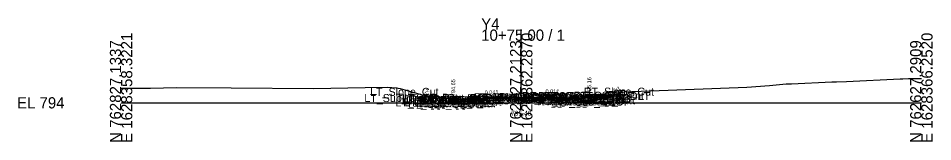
# Model space of a CAD drawing. Extents: x -26 to 203, y -10 to 3017.
# Drawn here: x -25.7 to 202.8, y 1490.3 to 1521.1 of the extents above; entities that cross this region are included whole.
import ezdxf

# ---------------------------------------------------------------- set-up
doc = ezdxf.new("R2010")
doc.units = 0
for name, color, linetype in [('Default', 7, 'Continuous'), ('Exist CMT Pavement', 7, 'Continuous'), ('Exist Cross Section Cell', 7, 'Continuous'), ('Exist XS Center Line Elevation Label', 7, 'Continuous'), ('Exist XS Ground Line', 7, 'Continuous'), ('Prop CMT Conc Surface', 7, 'Continuous'), ('Prop CMT Concrete Structures', 7, 'Continuous'), ('Prop CMT Pvmt Course 1', 7, 'Continuous'), ('Prop CMT Pvmt Course 1 CG', 7, 'Continuous'), ('Prop CMT Pvmt Course 1 Wedge', 7, 'Continuous'), ('Prop CMT Pvmt Course 2', 7, 'Continuous'), ('Prop CMT Pvmt Course 3', 7, 'Continuous'), ('Prop CMT Pvmt Surface', 7, 'Continuous'), ('Prop CMT Pvmt Wedge Surface 1', 7, 'Continuous'), ('Prop CMT Pvmt Wedge Surface 2', 7, 'Continuous'), ('Prop CMT Pvmt Wedge Surface 3', 7, 'Continuous'), ('Prop CMT Slope Grass', 7, 'Continuous'), ('Prop CMT Subgrade Earthwork', 7, 'Continuous'), ('Prop XS Hydro Elevations', 7, 'Continuous'), ('Prop XS SE Text', 7, 'Continuous'), ('Prop XS Side Slope Text', 7, 'Continuous'), ('Scratch_Level_0', 7, 'Continuous')]:
    doc.layers.add(name, color=color, linetype=linetype)

msp = doc.modelspace()

# ---------------------------------------------------------------- linework, layer by layer
at = {"layer": 'Exist CMT Pavement'}
for points in [[(100, 1501.4), (99.81, 1501.41), (95.3, 1501.2), (88.98, 1500.91), (88.16, 1500.85), (85.17, 1500.61)], [(100, 1501.4), (104.1, 1501.33), (110.97, 1501.22), (114.02, 1501.06), (114.86, 1501.03)], [(114.86, 1501.03), (114.86, 1501.03)]]:
    msp.add_lwpolyline(points, dxfattribs=at)
at = {"layer": 'Exist Cross Section Cell'}
for p, q in [((100, 1500), (100, 1518.27)), ((0, 1500), (100, 1500)), ((100, 1500), (200, 1500))]:
    msp.add_line(p, q, dxfattribs=at)
at = {"layer": 'Exist XS Ground Line'}
msp.add_lwpolyline([(0, 1503.66), (7.35, 1503.64), (13.85, 1503.81), (27.47, 1503.77), (48.05, 1503.6), (61.03, 1503.8), (66.57, 1503.94), (68.77, 1503.75), (69.78, 1503.53), (75.58, 1501.87), (77.91, 1501.34), (80.15, 1501.12), (82.88, 1501.17), (84.63, 1500.87), (85.17, 1500.61), (88.16, 1500.85), (88.98, 1500.91), (95.3, 1501.2), (99.81, 1501.41), (104.1, 1501.33), (110.97, 1501.22), (114.02, 1501.06), (114.86, 1501.03), (115.37, 1501.41), (116.27, 1501.41), (118.87, 1501.42), (121.21, 1502.41), (122.08, 1502.79), (124.74, 1503.09), (125.62, 1503.2), (126.12, 1502.7), (127.62, 1502.78), (132.29, 1502.97), (156.36, 1503.86), (162.04, 1504.34), (166.18, 1504.7), (166.49, 1504.72), (167.55, 1504.77), (177.63, 1505.2), (178.77, 1505.2), (181.32, 1505.28), (194.67, 1505.97), (195.39, 1505.97), (196.8, 1506.05), (200, 1506.09)], dxfattribs=at)
at = {"layer": 'Prop CMT Conc Surface'}
for points in [[(117, 1501.16), (117, 1501.66), (117.5, 1501.66)], [(83, 1500.65), (83, 1501.15), (82.5, 1501.15)], [(85, 1500.81), (83, 1500.65)], [(115, 1501.26), (117, 1501.16)]]:
    msp.add_lwpolyline(points, dxfattribs=at)
at = {"layer": 'Prop CMT Concrete Structures'}
for points in [[(115, 1501.26), (117, 1501.16), (117, 1501.66), (117.5, 1501.66)], [(117.5, 1501.66), (117.5, 1500.65), (115, 1500.68)], [(117.5, 1501.66), (117.5, 1501.32)], [(122.5, 1501.42), (122.5, 1501.76)], [(85, 1500.81), (83, 1500.65), (83, 1501.15), (82.5, 1501.15)], [(82.5, 1501.15), (82.5, 1500.12), (85, 1500.23)], [(85, 1500.23), (85, 1500.81)], [(115, 1500.68), (115, 1501.26)], [(117.5, 1501.32), (122.5, 1501.42)]]:
    msp.add_lwpolyline(points, dxfattribs=at)
at = {"layer": 'Prop CMT Pvmt Course 1'}
for points in [[(100, 1501.43), (85, 1500.81)], [(85, 1500.81), (85, 1500.56)], [(85, 1500.56), (85.17, 1500.57)], [(85.17, 1500.69), (100, 1501.31)], [(85.17, 1500.57), (85.17, 1500.69)], [(100, 1501.18), (100, 1501.43)], [(100, 1501.43), (115, 1501.26)], [(100, 1501.18), (100, 1501.43)], [(100, 1501.31), (100, 1501.18), (100, 1501.18)], [(114.86, 1501.14), (100, 1501.31)], [(100, 1501.31), (100, 1501.18), (100, 1501.18)], [(114.86, 1501.01), (114.86, 1501.14)], [(115, 1501.01), (114.86, 1501.01)], [(115, 1501.26), (115, 1501.01)]]:
    msp.add_lwpolyline(points, dxfattribs=at)
at = {"layer": 'Prop CMT Pvmt Course 1 CG'}
for points in [[(85, 1500.23), (82, 1500.1), (81.65, 1499.75)], [(81.65, 1499.75), (85, 1499.89)], [(85, 1499.89), (85, 1500.23)], [(115, 1500.68), (118, 1500.64), (118.34, 1500.31)], [(115, 1500.34), (115, 1500.68)], [(118.34, 1500.31), (115, 1500.34)]]:
    msp.add_lwpolyline(points, dxfattribs=at)
at = {"layer": 'Prop CMT Pvmt Course 1 Wedge'}
for points in [[(85.17, 1500.69), (87.3, 1500.78)], [(87.3, 1500.78), (85.17, 1500.61)], [(85.17, 1500.61), (85.17, 1500.69)], [(114.86, 1501.03), (114.02, 1501.06), (112.01, 1501.17)], [(112.01, 1501.17), (114.02, 1501.15)], [(114.02, 1501.15), (114.86, 1501.14)], [(114.86, 1501.14), (114.86, 1501.03), (114.86, 1501.03)]]:
    msp.add_lwpolyline(points, dxfattribs=at)
at = {"layer": 'Prop CMT Pvmt Course 2'}
for points in [[(85.17, 1500.57), (85, 1500.56)], [(85, 1500.56), (85, 1500.23)], [(85, 1500.23), (85.17, 1500.23)], [(85.17, 1500.23), (85.17, 1500.57)], [(114.86, 1500.68), (114.86, 1501.01)], [(114.86, 1501.01), (115, 1501.01)], [(115, 1500.68), (114.86, 1500.68)], [(115, 1501.01), (115, 1500.68)]]:
    msp.add_lwpolyline(points, dxfattribs=at)
at = {"layer": 'Prop CMT Pvmt Course 3'}
for points in [[(85.17, 1500.23), (85, 1500.23)], [(85, 1500.23), (85, 1499.89)], [(85, 1499.89), (85.17, 1499.9)], [(85.17, 1499.9), (85.17, 1500.23)], [(114.86, 1500.68), (115, 1500.68)], [(114.86, 1500.34), (114.86, 1500.68)], [(115, 1500.34), (114.86, 1500.34)], [(115, 1500.68), (115, 1500.34)]]:
    msp.add_lwpolyline(points, dxfattribs=at)
at = {"layer": 'Prop CMT Pvmt Surface'}
for points in [[(100, 1501.43), (85, 1500.81)], [(100, 1501.43), (115, 1501.26)]]:
    msp.add_lwpolyline(points, dxfattribs=at)
at = {"layer": 'Prop CMT Pvmt Wedge Surface 1'}
for points in [[(85, 1500.56), (85, 1500.81)], [(85.17, 1500.57), (85, 1500.56)], [(100, 1501.31), (85.17, 1500.69)], [(85.17, 1500.69), (85.17, 1500.57)], [(100, 1501.31), (114.86, 1501.14)], [(114.86, 1501.14), (114.86, 1501.01)], [(114.86, 1501.01), (115, 1501.01)], [(115, 1501.01), (115, 1501.26)]]:
    msp.add_lwpolyline(points, dxfattribs=at)
at = {"layer": 'Prop CMT Pvmt Wedge Surface 2'}
for points in [[(100, 1501.18), (85, 1500.56)], [(85, 1500.56), (85, 1500.81)], [(100, 1501.18), (115, 1501.01)], [(115, 1501.01), (115, 1501.26)]]:
    msp.add_lwpolyline(points, dxfattribs=at)
at = {"layer": 'Prop CMT Pvmt Wedge Surface 3'}
for points in [[(100, 1500.85), (85, 1500.23)], [(85, 1500.23), (85, 1500.81)], [(100, 1500.85), (115, 1500.68)], [(115, 1500.68), (115, 1501.26)]]:
    msp.add_lwpolyline(points, dxfattribs=at)
at = {"layer": 'Prop CMT Slope Grass'}
for p, q in [((75.93, 1501.79), (77, 1501.26)), ((123, 1501.77), (125.7, 1503.12))]:
    msp.add_line(p, q, dxfattribs=at)
for points in [[(117.5, 1501.66), (123, 1501.77)], [(82.5, 1501.15), (77, 1501.26)]]:
    msp.add_lwpolyline(points, dxfattribs=at)
at = {"layer": 'Prop CMT Subgrade Earthwork'}
for points in [[(85, 1499.89), (81.65, 1499.75), (80.21, 1501.19)], [(85.17, 1499.9), (85, 1499.89)], [(85.17, 1499.9), (85.19, 1500.61)], [(114.86, 1500.34), (114.85, 1501.03)], [(114.86, 1500.34), (115, 1500.34)], [(115, 1500.34), (118.34, 1500.31), (119.39, 1501.36)]]:
    msp.add_lwpolyline(points, dxfattribs=at)

# ---------------------------------------------------------------- texts
at = {"layer": 'Default'}
msp.add_text('-', height=0.0001, dxfattribs=at).set_placement((0, 1500))
at = {"layer": 'Exist Cross Section Cell'}
for s, p in [('Y4', (90, 1518.27)), ('10+75.00 / 1', (90, 1515.47)), ('EL 794', (-26, 1498.6))]:
    msp.add_text(s, height=2.8, dxfattribs=at).set_placement(p)
for s, p in [('N 762827.1337', (0, 1490)), ('E 1628358.3221', (2.8, 1490)), ('N 762727.2123', (100, 1490)), ('E 1628362.2870', (102.8, 1490)), ('N 762627.2909', (200, 1490)), ('E 1628366.2520', (202.8, 1490))]:
    msp.add_text(s, height=2.8, rotation=90, dxfattribs=at).set_placement(p)
at = {"layer": 'Exist XS Center Line Elevation Label'}
msp.add_text('795.40', height=1.2, dxfattribs=at).set_placement((97.48, 1496.8))
at = {"layer": 'Prop XS Hydro Elevations'}
for s, p in [('795.16', (117.5, 1502.16)), ('794.65', (83.5, 1501.65))]:
    msp.add_text(s, height=1, rotation=90, dxfattribs=at).set_placement(p)
at = {"layer": 'Prop XS SE Text'}
for s, rotation, p in [('0.041', 2.3723, (90.89, 1502.05)), ('0.011', 359.3452, (106.07, 1502.36))]:
    msp.add_text(s, height=1, rotation=rotation, dxfattribs=at).set_placement(p)
at = {"layer": 'Prop XS Side Slope Text'}
for rotation, p in [(26.5651, (123.19, 1502.44)), (333.4349, (75.77, 1502.56))]:
    msp.add_text('2:1', height=1, rotation=rotation, dxfattribs=at).set_placement(p)
at = {"layer": 'Scratch_Level_0'}
for s, p in [('LT_Slope_Cut', (62.23, 1501.72)), ('RT_Slope_Cut', (115.64, 1501.78)), ('LT_Sub_Trench_Out_DLT', (60.78, 1500.19)), ('LT_CSLP_Pnt', (67.17, 1500.26)), ('LT_PV_Sub_Tie_Out', (70.13, 1499.61)), ('LT_CG_Top_Face', (70.26, 1500.15)), ('LT_CG_Top_BOC', (70.78, 1500.15)), ('LT_CG_Top_Gut', (71.24, 1499.65)), ('LT_PV_OEEOP_EG', (72.72, 1499.61)), ('LT_PV2_OEEOP', (74.48, 1499.57)), ('LT_PV1_OEEOP', (75.05, 1499.69)), ('LT_PV2_OEOT', (75.17, 1499.56)), ('LT_PV1_OEOT', (75.74, 1499.81)), ('RT_PV_IEEOP_EG', (88.14, 1500.4)), ('LT_PV_IEEOP_EG', (88.19, 1500.4)), ('RT_PV2_IEEOP', (89.91, 1500.18)), ('RT_PV3_IEEOP', (89.91, 1499.85)), ('LT_PV2_IEEOP', (89.95, 1500.18)), ('LT_PV3_IEEOP', (89.95, 1499.85)), ('RT_PV1_IEEOP', (90.47, 1500.31)), ('LT_PV1_IEEOP', (90.52, 1500.31)), ('PV2_PGL', (93.91, 1500.18)), ('PV1_PGL', (94.47, 1500.43)), ('RT_PV_Sub_Tie_Out', (99.74, 1500.03)), ('RT_Sub_Trench_Out_DLT', (100.25, 1500.7)), ('RT_PV_OEEOP_EG', (102.36, 1500.03)), ('RT_PV2_OEEOP', (104.12, 1500.01)), ('RT_PV3_OEEOP', (104.12, 1499.68)), ('RT_CG_Top_Face', (104.21, 1500.66)), ('RT_CG1_Shelf_Out', (104.5, 1499.64)), ('RT_PV1_OEEOP', (104.69, 1500.14)), ('RT_CG_Bot_IE', (104.87, 1499.68)), ('RT_PV2_OEOT', (105.13, 1500.01)), ('RT_PV3_OEOT', (105.13, 1499.68)), ('RT_CG_Top_Gut', (105.19, 1500.16)), ('RT_PV1_OEOT', (105.69, 1500.26)), ('RT_CG_Top_BOC', (105.74, 1500.66)), ('RT_CG_Bot_BOC', (105.77, 1499.65)), ('RT_CSLP_Pnt', (113.13, 1500.77)), ('LT_CG1_Shelf_Out', (68.55, 1499.1)), ('LT_CG_Bot_BOC', (70.81, 1499.12)), ('LT_Sub_OEOP', (71.76, 1498.75)), ('LT_Sub_OEEOP', (74.39, 1498.9)), ('LT_PV3_OEEOP', (74.48, 1499.23)), ('LT_CG_Bot_IE', (74.91, 1499.23)), ('LT_Sub_OEOT', (75.08, 1498.89)), ('LT_PV3_OEOT', (75.17, 1499.23)), ('RT_Sub_OEEOP', (104.03, 1499.34)), ('RT_Sub_OEOT', (105.03, 1499.34)), ('RT_Sub_OEOP', (108.4, 1499.31))]:
    msp.add_text(s, height=2, dxfattribs=at).set_placement(p)

doc.saveas('drawing.dxf')
